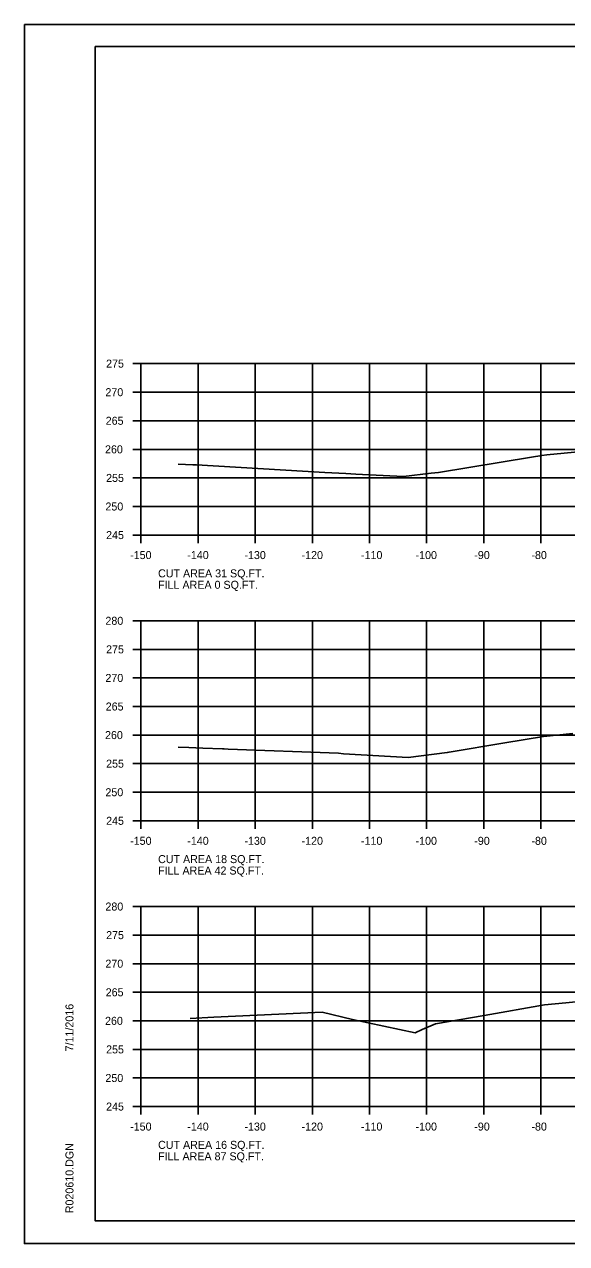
# Model space of a CAD drawing. Extents: x 1103485 to 1107180, y 2010593 to 2011873.
# Drawn here: x 1106846.8 to 1106941.7, y 2011019.5 to 2011232.8 of the extents above; entities that cross this region are included whole.
import ezdxf

# ---------------------------------------------------------------- set-up
doc = ezdxf.new("R2010")
doc.units = 0
for name, color, linetype in [('R_Axis', 7, 'Continuous'), ('R_Axis Annot', 7, 'Continuous'), ('R_Border', 7, 'Continuous'), ('R_Exist Surface', 7, 'Continuous'), ('R_Grid', 7, 'Continuous'), ('R_No Plot', 7, 'Continuous')]:
    doc.layers.add(name, color=color, linetype=linetype)

msp = doc.modelspace()

# ---------------------------------------------------------------- linework, layer by layer
at = {"layer": 'R_Axis'}
for p, q in [((1106865.78, 2011173.49), (1106867.18, 2011173.49)), ((1106867.18, 2011143.49), (1106867.18, 2011173.49)), ((1106865.78, 2011168.49), (1106867.18, 2011168.49)), ((1106865.78, 2011163.49), (1106867.18, 2011163.49)), ((1106865.78, 2011158.49), (1106867.18, 2011158.49)), ((1106865.78, 2011153.49), (1106867.18, 2011153.49)), ((1106865.78, 2011148.49), (1106867.18, 2011148.49)), ((1106865.78, 2011143.49), (1106867.18, 2011143.49)), ((1106867.18, 2011143.49), (1107167.18, 2011143.49)), ((1106867.18, 2011142.09), (1106867.18, 2011143.49)), ((1106877.18, 2011142.09), (1106877.18, 2011143.49)), ((1106887.18, 2011142.09), (1106887.18, 2011143.49)), ((1106897.18, 2011142.09), (1106897.18, 2011143.49)), ((1106907.18, 2011142.09), (1106907.18, 2011143.49)), ((1106917.18, 2011142.09), (1106917.18, 2011143.49)), ((1106927.18, 2011142.09), (1106927.18, 2011143.49)), ((1106937.18, 2011142.09), (1106937.18, 2011143.49)), ((1106865.78, 2011128.49), (1106867.18, 2011128.49)), ((1106867.18, 2011093.49), (1106867.18, 2011128.49)), ((1106865.78, 2011123.49), (1106867.18, 2011123.49)), ((1106865.78, 2011118.49), (1106867.18, 2011118.49)), ((1106865.78, 2011113.49), (1106867.18, 2011113.49)), ((1106865.78, 2011108.49), (1106867.18, 2011108.49)), ((1106865.78, 2011103.49), (1106867.18, 2011103.49)), ((1106865.78, 2011098.49), (1106867.18, 2011098.49)), ((1106865.78, 2011093.49), (1106867.18, 2011093.49)), ((1106867.18, 2011093.49), (1107167.18, 2011093.49)), ((1106867.18, 2011092.09), (1106867.18, 2011093.49)), ((1106877.18, 2011092.09), (1106877.18, 2011093.49)), ((1106887.18, 2011092.09), (1106887.18, 2011093.49)), ((1106897.18, 2011092.09), (1106897.18, 2011093.49)), ((1106907.18, 2011092.09), (1106907.18, 2011093.49)), ((1106917.18, 2011092.09), (1106917.18, 2011093.49)), ((1106927.18, 2011092.09), (1106927.18, 2011093.49)), ((1106937.18, 2011092.09), (1106937.18, 2011093.49)), ((1106865.78, 2011078.49), (1106867.18, 2011078.49)), ((1106867.18, 2011043.49), (1106867.18, 2011078.49)), ((1106865.78, 2011073.49), (1106867.18, 2011073.49)), ((1106865.78, 2011068.49), (1106867.18, 2011068.49)), ((1106865.78, 2011063.49), (1106867.18, 2011063.49)), ((1106865.78, 2011058.49), (1106867.18, 2011058.49)), ((1106865.78, 2011053.49), (1106867.18, 2011053.49)), ((1106865.78, 2011048.49), (1106867.18, 2011048.49)), ((1106865.78, 2011043.49), (1106867.18, 2011043.49)), ((1106867.18, 2011043.49), (1107167.18, 2011043.49)), ((1106867.18, 2011042.09), (1106867.18, 2011043.49)), ((1106877.18, 2011042.09), (1106877.18, 2011043.49)), ((1106887.18, 2011042.09), (1106887.18, 2011043.49)), ((1106897.18, 2011042.09), (1106897.18, 2011043.49)), ((1106907.18, 2011042.09), (1106907.18, 2011043.49)), ((1106917.18, 2011042.09), (1106917.18, 2011043.49)), ((1106927.18, 2011042.09), (1106927.18, 2011043.49)), ((1106937.18, 2011042.09), (1106937.18, 2011043.49))]:
    msp.add_line(p, q, dxfattribs=at)
at = {"layer": 'R_Border'}
for p, q in [((1106859.18, 2011228.95), (1107175.36, 2011228.95)), ((1106859.18, 2011023.49), (1106859.18, 2011228.95)), ((1106859.18, 2011023.49), (1106859.18, 2011023.49)), ((1107175.36, 2011023.49), (1106859.18, 2011023.49))]:
    msp.add_line(p, q, dxfattribs=at)
at = {"layer": 'R_Exist Surface'}
for points in [[(1106873.69, 2011155.9), (1106876.24, 2011155.79), (1106876.93, 2011155.76), (1106899.39, 2011154.43), (1106903.06, 2011154.24), (1106904.77, 2011154.15), (1106913.15, 2011153.71), (1106918, 2011154.31), (1106919.24, 2011154.46), (1106935.52, 2011157.13), (1106937.36, 2011157.44), (1106938.22, 2011157.52), (1106946.11, 2011158.31)], [(1106873.68, 2011106.38), (1106875.54, 2011106.3), (1106878.02, 2011106.2), (1106881.47, 2011106.06), (1106881.75, 2011106.06), (1106882.46, 2011106.05), (1106901.78, 2011105.3), (1106902.65, 2011105.2), (1106913.95, 2011104.56), (1106920.78, 2011105.44), (1106920.85, 2011105.46), (1106921.11, 2011105.51), (1106930.87, 2011107.12), (1106937.63, 2011108.24), (1106942.74, 2011108.76)], [(1106875.77, 2011058.91), (1106879.91, 2011059.11), (1106898.87, 2011060.02), (1106904.2, 2011058.73), (1106915.2, 2011056.37), (1106916.4, 2011056.96), (1106918.76, 2011057.98), (1106927.23, 2011059.43), (1106937.83, 2011061.29), (1106941.53, 2011061.65), (1106946.2, 2011062.1)]]:
    msp.add_lwpolyline(points, dxfattribs=at)
at = {"layer": 'R_Grid'}
for p, q in [((1106867.18, 2011173.49), (1107167.18, 2011173.49)), ((1106867.18, 2011143.49), (1106867.18, 2011173.49)), ((1106877.18, 2011143.49), (1106877.18, 2011173.49)), ((1106887.18, 2011143.49), (1106887.18, 2011173.49)), ((1106897.18, 2011143.49), (1106897.18, 2011173.49)), ((1106907.18, 2011143.49), (1106907.18, 2011173.49)), ((1106917.18, 2011143.49), (1106917.18, 2011173.49)), ((1106927.18, 2011143.49), (1106927.18, 2011173.49)), ((1106937.18, 2011143.49), (1106937.18, 2011173.49)), ((1106867.18, 2011168.49), (1107167.18, 2011168.49)), ((1106867.18, 2011163.49), (1107167.18, 2011163.49)), ((1106867.18, 2011158.49), (1107167.18, 2011158.49)), ((1106867.18, 2011153.49), (1107167.18, 2011153.49)), ((1106867.18, 2011148.49), (1107167.18, 2011148.49)), ((1106867.18, 2011143.49), (1107167.18, 2011143.49)), ((1106867.18, 2011128.49), (1107167.18, 2011128.49)), ((1106867.18, 2011093.49), (1106867.18, 2011128.49)), ((1106877.18, 2011093.49), (1106877.18, 2011128.49)), ((1106887.18, 2011093.49), (1106887.18, 2011128.49)), ((1106897.18, 2011093.49), (1106897.18, 2011128.49)), ((1106907.18, 2011093.49), (1106907.18, 2011128.49)), ((1106917.18, 2011093.49), (1106917.18, 2011128.49)), ((1106927.18, 2011093.49), (1106927.18, 2011128.49)), ((1106937.18, 2011093.49), (1106937.18, 2011128.49)), ((1106867.18, 2011123.49), (1107167.18, 2011123.49)), ((1106867.18, 2011118.49), (1107167.18, 2011118.49)), ((1106867.18, 2011113.49), (1107167.18, 2011113.49)), ((1106867.18, 2011108.49), (1107167.18, 2011108.49)), ((1106867.18, 2011103.49), (1107167.18, 2011103.49)), ((1106867.18, 2011098.49), (1107167.18, 2011098.49)), ((1106867.18, 2011093.49), (1107167.18, 2011093.49)), ((1106867.18, 2011078.49), (1107167.18, 2011078.49)), ((1106867.18, 2011043.49), (1106867.18, 2011078.49)), ((1106877.18, 2011043.49), (1106877.18, 2011078.49)), ((1106887.18, 2011043.49), (1106887.18, 2011078.49)), ((1106897.18, 2011043.49), (1106897.18, 2011078.49)), ((1106907.18, 2011043.49), (1106907.18, 2011078.49)), ((1106917.18, 2011043.49), (1106917.18, 2011078.49)), ((1106927.18, 2011043.49), (1106927.18, 2011078.49)), ((1106937.18, 2011043.49), (1106937.18, 2011078.49)), ((1106867.18, 2011073.49), (1107167.18, 2011073.49)), ((1106867.18, 2011068.49), (1107167.18, 2011068.49)), ((1106867.18, 2011063.49), (1107167.18, 2011063.49)), ((1106867.18, 2011058.49), (1107167.18, 2011058.49)), ((1106867.18, 2011053.49), (1107167.18, 2011053.49)), ((1106867.18, 2011048.49), (1107167.18, 2011048.49)), ((1106867.18, 2011043.49), (1107167.18, 2011043.49))]:
    msp.add_line(p, q, dxfattribs=at)
at = {"layer": 'R_No Plot'}
for p, q in [((1106846.78, 2011232.85), (1107180.12, 2011232.85)), ((1106846.78, 2011019.51), (1107180.12, 2011019.51))]:
    msp.add_line(p, q, dxfattribs=at)
for points in [[(1106846.78, 2011232.85), (1107180.12, 2011232.85), (1107180.12, 2011019.51), (1106846.78, 2011019.51)], [(1107093.1, 2011228.95), (1107093.1, 2011219.07), (1107128.84, 2011219.07), (1107128.84, 2011216.15), (1107152.04, 2011216.15), (1107152.04, 2011191.82), (1107175.36, 2011191.82), (1107175.36, 2011023.49), (1106859.18, 2011023.49), (1106859.18, 2011228.95)]]:
    msp.add_lwpolyline(points, close=True, dxfattribs=at)

# ---------------------------------------------------------------- texts
at = {"layer": 'R_Axis Annot'}
for s, p in [('275', (1106861.08, 2011172.79)), ('270', (1106860.96, 2011167.79)), ('265', (1106861.01, 2011162.79)), ('260', (1106860.89, 2011157.79)), ('255', (1106861.08, 2011152.79)), ('250', (1106860.96, 2011147.79)), ('245', (1106861.08, 2011142.79)), ('-150', (1106865.29, 2011139.29)), ('-140', (1106875.29, 2011139.29)), ('-130', (1106885.29, 2011139.29)), ('-120', (1106895.29, 2011139.29)), ('-110', (1106905.69, 2011139.29)), ('-100', (1106915.24, 2011139.29)), ('-90', (1106925.52, 2011139.29)), ('-80', (1106935.52, 2011139.29)), ('CUT AREA 31 SQ.FT.', (1106870.18, 2011136.09)), ('FILL AREA 0 SQ.FT.', (1106870.18, 2011134.09)), ('280', (1106860.96, 2011127.79)), ('275', (1106861.08, 2011122.79)), ('270', (1106860.96, 2011117.79)), ('265', (1106861.01, 2011112.79)), ('260', (1106860.89, 2011107.79)), ('255', (1106861.08, 2011102.79)), ('250', (1106860.96, 2011097.79)), ('245', (1106861.08, 2011092.79)), ('-150', (1106865.29, 2011089.29)), ('-140', (1106875.29, 2011089.29)), ('-130', (1106885.29, 2011089.29)), ('-120', (1106895.29, 2011089.29)), ('-110', (1106905.69, 2011089.29)), ('-100', (1106915.24, 2011089.29)), ('-90', (1106925.52, 2011089.29)), ('-80', (1106935.52, 2011089.29)), ('CUT AREA 18 SQ.FT.', (1106870.18, 2011086.09)), ('FILL AREA 42 SQ.FT.', (1106870.18, 2011084.09)), ('280', (1106860.96, 2011077.79)), ('275', (1106861.08, 2011072.79)), ('270', (1106860.96, 2011067.79)), ('265', (1106861.01, 2011062.79)), ('260', (1106860.89, 2011057.79)), ('255', (1106861.08, 2011052.79)), ('250', (1106860.96, 2011047.79)), ('245', (1106861.08, 2011042.79)), ('-150', (1106865.29, 2011039.29)), ('-140', (1106875.29, 2011039.29)), ('-130', (1106885.29, 2011039.29)), ('-120', (1106895.29, 2011039.29)), ('-110', (1106905.69, 2011039.29)), ('-100', (1106915.24, 2011039.29)), ('-90', (1106925.52, 2011039.29)), ('-80', (1106935.52, 2011039.29)), ('CUT AREA 16 SQ.FT.', (1106870.18, 2011036.09)), ('FILL AREA 87 SQ.FT.', (1106870.18, 2011034.09))]:
    msp.add_text(s, height=1.4, dxfattribs=at).set_placement(p)
at = {"layer": 'R_Border'}
for s, p in [('7/11/2016', (1106855.37, 2011053.14)), ('R020610.DGN', (1106855.37, 2011024.82))]:
    msp.add_text(s, height=1.4, rotation=90, dxfattribs=at).set_placement(p)

doc.saveas('drawing.dxf')
